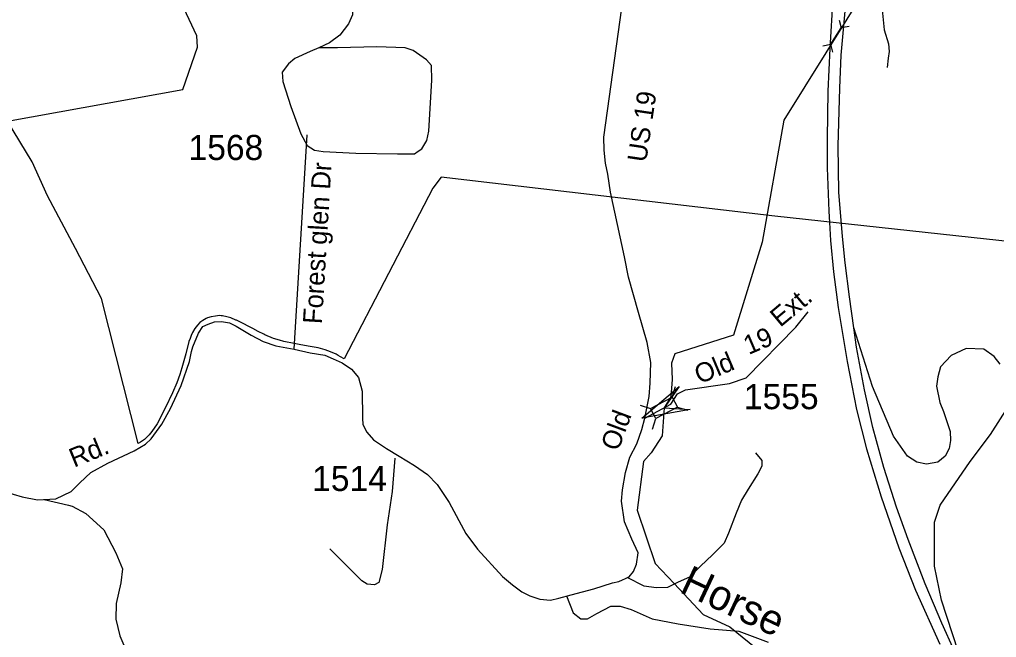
# Model space of a CAD drawing. Extents: x 990631 to 1056237, y 535999 to 585651.
# Drawn here: x 1039191 to 1044054, y 554992 to 558069 of the extents above; entities that cross this region are included whole.
import ezdxf

# ---------------------------------------------------------------- set-up
doc = ezdxf.new("R2010")
doc.units = 0
for name, color, linetype in [('Exist Boundary Political City Limit New', 7, 'Continuous'), ('Exist Hydrographic Creek Single Shore', 7, 'Continuous'), ('Exist Hydrographic Creek Single Shore Label', 7, 'Continuous'), ('Exist Road Non-System Type 51', 7, 'Continuous'), ('Exist Road Primary Interstate Divided Center Attributed', 7, 'Continuous'), ('Exist Road Primary Interstate Ramp 1 Lane Attributed', 7, 'Continuous'), ('Exist Road Primary US Structure Standard Bridge CELL', 7, 'Continuous'), ('Exist Road Secondary Added by HereSay', 7, 'Continuous'), ('Exist Road Secondary Structure Culvert CELL', 7, 'Continuous'), ('Exist Road Secondary Structure Standard Bridge Attributed CELL', 7, 'Continuous'), ('Exist Road Secondary Type 41 Attributed', 7, 'Continuous'), ('Exist Road Secondary Type 51 Attributed', 7, 'Continuous'), ('Exist Road Secondary Type 51 Label', 7, 'Continuous'), ('Exist Road Secondary Type 51 Number Label', 7, 'Continuous')]:
    doc.layers.add(name, color=color, linetype=linetype)

msp = doc.modelspace()

# ---------------------------------------------------------------- linework, layer by layer
at = {"layer": 'Exist Boundary Political City Limit New'}
for points in [[(1040045.1, 556496.5), (1040039.9, 556481.7), (1040034.4, 556465.9), (1040018.7, 556405.1), (1040000, 556334.4), (1039989.6, 556301.4), (1039974.1, 556260.4), (1039952.6, 556210.5), (1039917.8, 556136.9), (1039875.8, 556056.5), (1039850, 556017.9), (1039836.8, 556001.6), (1039824, 555988.6), (1039813.1, 555978.6), (1039794.2, 555964.4), (1039781.6, 555958.6), (1039599.9, 556680.9), (1039469.6, 556928.9), (1039331.2, 557191.9), (1039254.6, 557360.5), (1039130.8, 557564), (1040003.6, 557720.6), (1040076.8, 557930.9), (1040073.9, 557988.5), (1039959.6, 558234.4)], [(1044370.9, 556935.4), (1042951.9, 557090.9), (1041289.6, 557284.5), (1041249.4, 557229.3), (1040807.4, 556379.4), (1040789.6, 556390), (1040778.2, 556396.3), (1040767.1, 556402.5), (1040739.8, 556414.9), (1040712.4, 556424.9), (1040678, 556434.1), (1040638.4, 556441.9), (1040591.2, 556449.7), (1040550.1, 556457.2), (1040514.8, 556463.8), (1040506.3, 556466.2), (1040484.7, 556472.3), (1040454.9, 556481), (1040413.1, 556499.1), (1040406.8, 556502.4), (1040379.5, 556515.8), (1040352.6, 556530), (1040339.6, 556536.6), (1040297.6, 556558.3), (1040270.7, 556572.1), (1040268.6, 556573), (1040242.4, 556583.4), (1040223.2, 556589.2), (1040201.9, 556593.4), (1040195.8, 556594.3), (1040186.2, 556594.9), (1040166.2, 556592.3), (1040146, 556588.7), (1040127.1, 556584.3), (1040120, 556581.1), (1040103.9, 556571.1), (1040088.8, 556559.8), (1040077.4, 556547.7), (1040063.4, 556530), (1040052.5, 556511.6), (1040045.1, 556496.5)]]:
    msp.add_lwpolyline(points, dxfattribs=at)
at = {"layer": 'Exist Hydrographic Creek Single Shore'}
msp.add_lwpolyline([(1043607.2, 559178), (1043538.5, 558788.4), (1043413.3, 558240.8), (1042995.9, 557567.8), (1042888.8, 556961), (1042746, 556496.9), (1042454.1, 556404.5), (1042436, 556357.5), (1042440.2, 556277.3), (1042432.8, 556189.7), (1042400.7, 556136.2), (1042389.5, 555996.8), (1042336.1, 555911.3), (1042297.6, 555868.5), (1042265.3, 555626.8), (1042354.9, 555361.2), (1042449.8, 555261), (1042595.1, 555107.1), (1042726.7, 555045.3), (1042954.2, 554860.3)], dxfattribs=at)
at = {"layer": 'Exist Road Non-System Type 51'}
for points in [[(1043847, 558789.8), (1043813.6, 558682.8), (1043793.5, 558617.4), (1043765, 558544.4), (1043727.2, 558483.5), (1043703.3, 558430.2), (1043643, 558356.1), (1043570.2, 558270.4), (1043520.4, 558218), (1043498.7, 558166.6), (1043483.5, 558127.1), (1043486.6, 558101), (1043495.9, 558018.6), (1043517.7, 557947.9), (1043520.6, 557909.6), (1043515.5, 557877.7), (1043509.9, 557830)], [(1040624.8, 558479), (1040632.1, 558392.6), (1040644.6, 558346.1), (1040675.4, 558307.3), (1040733.6, 558249.3), (1040786.5, 558213.6), (1040829.4, 558174.1), (1040850, 558137.5), (1040848.7, 558093.5), (1040829.2, 558048.1), (1040785.5, 557991.3), (1040734.1, 557953), (1040681.4, 557928.8)], [(1040681.4, 557928.8), (1040638.8, 557910.1), (1040561.4, 557874.6), (1040530.7, 557849.4), (1040499.2, 557806.4), (1040501.7, 557760.4), (1040541.8, 557636.9), (1040591.5, 557499.3), (1040623.7, 557442.2), (1040658.9, 557419.1), (1040702.8, 557411.6), (1040864.7, 557404.5), (1041072.6, 557399.7), (1041156.7, 557401.1), (1041175.2, 557414.5), (1041193.6, 557425.9), (1041218.9, 557467.2), (1041228.4, 557512.9), (1041244.5, 557766.6), (1041242.8, 557840.7), (1041217.8, 557869.4), (1041151.3, 557915.8), (1041111.5, 557929), (1040969.8, 557933.4), (1040773.4, 557927.8), (1040681.4, 557928.8)], [(1042854.1, 555911.7), (1042886.9, 555872.7), (1042885.9, 555844.7), (1042866.8, 555807.2), (1042818.2, 555730.8), (1042784.5, 555675.8), (1042758.4, 555610.6), (1042721.2, 555511.7), (1042699.6, 555462.3), (1042641.6, 555404.2), (1042581.8, 555348), (1042530.1, 555293.6), (1042467.1, 555265.7), (1042416.2, 555241.3), (1042360.2, 555239), (1042300.3, 555247), (1042216.4, 555290.5)], [(1041059.9, 555885.2), (1041046.8, 555719.5), (1041021.4, 555552.3), (1040996.1, 555330.9), (1040980, 555265.4), (1040957.8, 555254.1), (1040921.8, 555257.2), (1040894.4, 555274.2), (1040735.3, 555433.2)], [(1039313.7, 555679.7), (1039434.9, 555651.7), (1039454, 555645.7), (1039522, 555609.3), (1039611.4, 555528.5), (1039669.9, 555414.4), (1039703.3, 555333.3), (1039695.1, 555263.5), (1039671.8, 555162.1), (1039671.3, 555084.1), (1039690.6, 554999.5), (1039731.4, 554904)], [(1041913.8, 555198.7), (1041947.3, 555115), (1041984.9, 555085.7), (1042018.3, 555085.7), (1042064.3, 555110.8), (1042135.4, 555148.5), (1042181.3, 555148.5), (1042235.7, 555131.8), (1042340.2, 555085.7), (1042469.8, 555060.7), (1042628.6, 555035.6), (1042771.9, 555023.7), (1042918.2, 554969.4)]]:
    msp.add_lwpolyline(points, dxfattribs=at)
at = {"layer": 'Exist Road Primary Interstate Divided Center Attributed'}
for points in [[(1043250.4, 558268.7), (1043240.6, 558179.7), (1043224.5, 557925.1), (1043215.2, 557712), (1043212.5, 557477.5), (1043212.5, 557331.5), (1043219.2, 557115.7), (1043223.2, 557058.1), (1043228.6, 556968.3), (1043243.3, 556812.9), (1043266.1, 556634.6), (1043311.6, 556366.6), (1043358.5, 556128.1), (1043408.1, 555931.1), (1043480.4, 555692.6), (1043568.8, 555438), (1043651.8, 555227.6), (1043772.4, 554958.2)], [(1043344.5, 556534.7), (1043322.3, 556688.2), (1043300.9, 556857.1), (1043287.5, 556988.4), (1043270.1, 557209.5), (1043266.1, 557440), (1043274.1, 557726.8), (1043282.1, 557891.6), (1043305.8, 558165.9)], [(1043892.8, 554836.9), (1043844.7, 554927.4), (1043781.8, 555062.7), (1043698.7, 555259.7), (1043614.3, 555480.8), (1043556.7, 555640.3), (1043493.8, 555838.6), (1043438.9, 556038.3), (1043397.3, 556225.9), (1043358.5, 556437.6), (1043344.5, 556534.7)]]:
    msp.add_lwpolyline(points, dxfattribs=at)
at = {"layer": 'Exist Road Primary Interstate Ramp 1 Lane Attributed'}
for points in [[(1044072.9, 556352.6), (1044043, 556391), (1043991.6, 556428.4), (1043903.4, 556431.6), (1043829.5, 556396.8), (1043776.6, 556339.6), (1043762.5, 556290.5), (1043755.5, 556243.8), (1043771.9, 556162), (1043790.6, 556117.6), (1043823.3, 556017.1), (1043825.6, 555972.7), (1043819.8, 555933.8), (1043799.9, 555895.6), (1043763.3, 555864.3), (1043706.9, 555855.6), (1043657.4, 555865.2), (1043611.3, 555894.7), (1043541.8, 555994.6), (1043437.6, 556242.2), (1043344.5, 556534.7)], [(1043892.8, 554836.9), (1043780.7, 555178), (1043746, 555347.4), (1043746.2, 555566), (1043774.2, 555650.2), (1043924.1, 555868.6), (1044024.3, 556003.1), (1044113.1, 556140.9)]]:
    msp.add_lwpolyline(points, dxfattribs=at)
at = {"layer": 'Exist Road Primary US Structure Standard Bridge CELL'}
for p, q in [((1042439.9, 556188.7), (1042456.3, 556241.3)), ((1042280, 556149.2), (1042332.7, 556132.8)), ((1042465.5, 556139.8), (1042518.2, 556123.3)), ((1042342.5, 556030.1), (1042358.9, 556082.7))]:
    msp.add_line(p, q, dxfattribs=at)
msp.add_lwpolyline([(1042332.7, 556132.8), (1042439.8, 556188.9), (1042466, 556138.9), (1042358.9, 556082.7)], close=True, dxfattribs=at)
at = {"layer": 'Exist Road Secondary Added by HereSay'}
msp.add_line((1040559.1, 556427.6), (1040623.6, 557495.3), dxfattribs=at)
at = {"layer": 'Exist Road Secondary Structure Culvert CELL'}
for p, q in [((1043271.8, 558066.9), (1043281.7, 558027.5)), ((1043229.8, 557945.9), (1043281.7, 558027.5)), ((1043321.6, 558035.2), (1043281.7, 558027.5)), ((1043189.9, 557938.1), (1043229.8, 557945.9)), ((1043239.7, 557906.5), (1043229.8, 557945.9))]:
    msp.add_line(p, q, dxfattribs=at)
at = {"layer": 'Exist Road Secondary Structure Standard Bridge Attributed CELL'}
msp.add_lwpolyline([(1042529.3, 556127.4), (1042289.3, 556084.4), (1042475.7, 556241.6), (1042399.6, 556136.2)], close=True, dxfattribs=at)
at = {"layer": 'Exist Road Secondary Type 41 Attributed'}
msp.add_lwpolyline([(1042304.4, 556084.3), (1042432.9, 556154.1), (1042467.4, 556205.9), (1042506.3, 556226.1), (1042725, 556256.3), (1042808.4, 556285.1), (1043055.9, 556537), (1043117.8, 556613.3)], dxfattribs=at)
at = {"layer": 'Exist Road Secondary Type 51 Attributed'}
for points in [[(1042304.4, 556084.3), (1042325, 556191.5), (1042330.8, 556259.2), (1042333.6, 556361.4), (1042314.9, 556460.7), (1042271.8, 556610.4), (1042222.8, 556786.1), (1042202.7, 556888.3), (1042133.6, 557209.3), (1042119.3, 557298.6), (1042107.7, 557353.3), (1042102, 557418.1), (1042100.6, 557484.3), (1042207, 558260.3), (1042266.4, 558711.7), (1042300.1, 559037.7), (1042302.4, 559163.3)], [(1039115.1, 555719.3), (1039204.3, 555691.9), (1039280.6, 555677.5), (1039371.2, 555683.3), (1039447.5, 555719.3), (1039490.6, 555762.5), (1039546.7, 555812.9), (1039630.2, 555860.4), (1039762.6, 555920.8), (1039818.7, 555954), (1039846, 555981.3), (1039899.2, 556054.7), (1039942.4, 556132.5), (1039995.6, 556246.2), (1040037.4, 556365.7), (1040047.4, 556416.1), (1040053.2, 556439.9), (1040082, 556508.2), (1040103.5, 556539.9), (1040130.9, 556552.9), (1040162.5, 556564.4), (1040197.1, 556565.8), (1040235.9, 556558.6), (1040269, 556542.8), (1040343.8, 556496.7), (1040404.2, 556466.5), (1040467.6, 556444.9), (1040559.1, 556427.6)], [(1040559.1, 556427.6), (1040638.8, 556410.3), (1040710.7, 556397.4), (1040752.4, 556380.1), (1040797, 556359.9), (1040843.1, 556328.3), (1040879, 556286.5), (1040896.3, 556218.9), (1040899.2, 556085), (1040900.6, 556053.3), (1040920.8, 556014.4), (1040953.9, 555977), (1041017.2, 555933.8), (1041081.9, 555894.9), (1041156.7, 555848.9), (1041221.5, 555804.2), (1041270.4, 555753.8), (1041330.8, 555664.6), (1041412.8, 555510.5), (1041470.4, 555431.4), (1041595.5, 555296), (1041645.9, 555254.3), (1041691.9, 555219.7), (1041732.2, 555199.6), (1041781.1, 555182.3), (1041834.4, 555178), (1041876.1, 555188.1), (1041936.7, 555204.5), (1042049.8, 555235.1), (1042143.7, 555264.4), (1042173.9, 555271.6), (1042225.7, 555294.6), (1042247.3, 555320.5), (1042263.1, 555357.9), (1042270.3, 555414.1), (1042239.8, 555481.1), (1042202.5, 555568.3), (1042188.3, 555670.4), (1042192.6, 555727.9), (1042207, 555812.9), (1042228.6, 555890.6), (1042264.6, 555956.8), (1042289, 556027.4), (1042304.4, 556084.3)]]:
    msp.add_lwpolyline(points, dxfattribs=at)

# ---------------------------------------------------------------- texts
at = {"layer": 'Exist Hydrographic Creek Single Shore Label'}
msp.add_text('Horse', height=150, rotation=334.845, dxfattribs=at).set_placement((1042471.4, 555219.6))
at = {"layer": 'Exist Road Secondary Type 51 Label'}
for s, rotation, p in [('US 19', 81.5288, (1042310.5, 557355.4)), ('Forest glen Dr', 86.5444, (1040696.4, 556551.3)), ('Ext.', 39.9564, (1042978.1, 556533.9)), ('19', 23.2357, (1042820.8, 556398.4)), ('Old', 22.8506, (1042575.9, 556252.6)), ('Old', 69.6367, (1042171, 555915.5)), ('Rd.', 22.2706, (1039462.6, 555837.4))]:
    msp.add_text(s, height=95, rotation=rotation, dxfattribs=at).set_placement(p)
at = {"layer": 'Exist Road Secondary Type 51 Number Label'}
for s, p in [('1568', (1040032.7, 557369.7)), ('1555', (1042797.3, 556128.9)), ('1514', (1040647.8, 555721.5))]:
    msp.add_text(s, height=125, dxfattribs=at).set_placement(p)

doc.saveas('drawing.dxf')
